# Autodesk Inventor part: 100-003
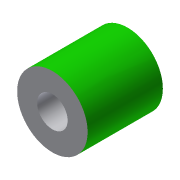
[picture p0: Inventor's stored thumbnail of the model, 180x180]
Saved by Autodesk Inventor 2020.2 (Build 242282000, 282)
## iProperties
Created: 2014-01
Part Number: 100-003
Material: Ogólny
Document SubType Name: Modeling
Designer: F.Stasiak
Density: 1 g/cm^3
Appearance: Biały
Manager: www.cadconsulting.pl
Company: Fabian Stasiak CAD Consulting
Author: F.Stasiak
Subject: Zbiór ćwiczeń. Autodesk Inventor 2020. Kurs podstawowy
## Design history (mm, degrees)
sketch "Szkic1"
  geometry: C1 r 7.5 at (0, 0); C2 r 3.25 at (0, 0); 1 further point
  constraints: 2 centre point, 2 coincident
  dimensions: "d0" = 15 diameter of C1; "d1" = 6.5 diameter of C2
extrude "Wyciągnięcie proste1" new body sketch "Szkic1" distance "d2" = 16; taper "d3" = 0 deg
node "Bryła1"
